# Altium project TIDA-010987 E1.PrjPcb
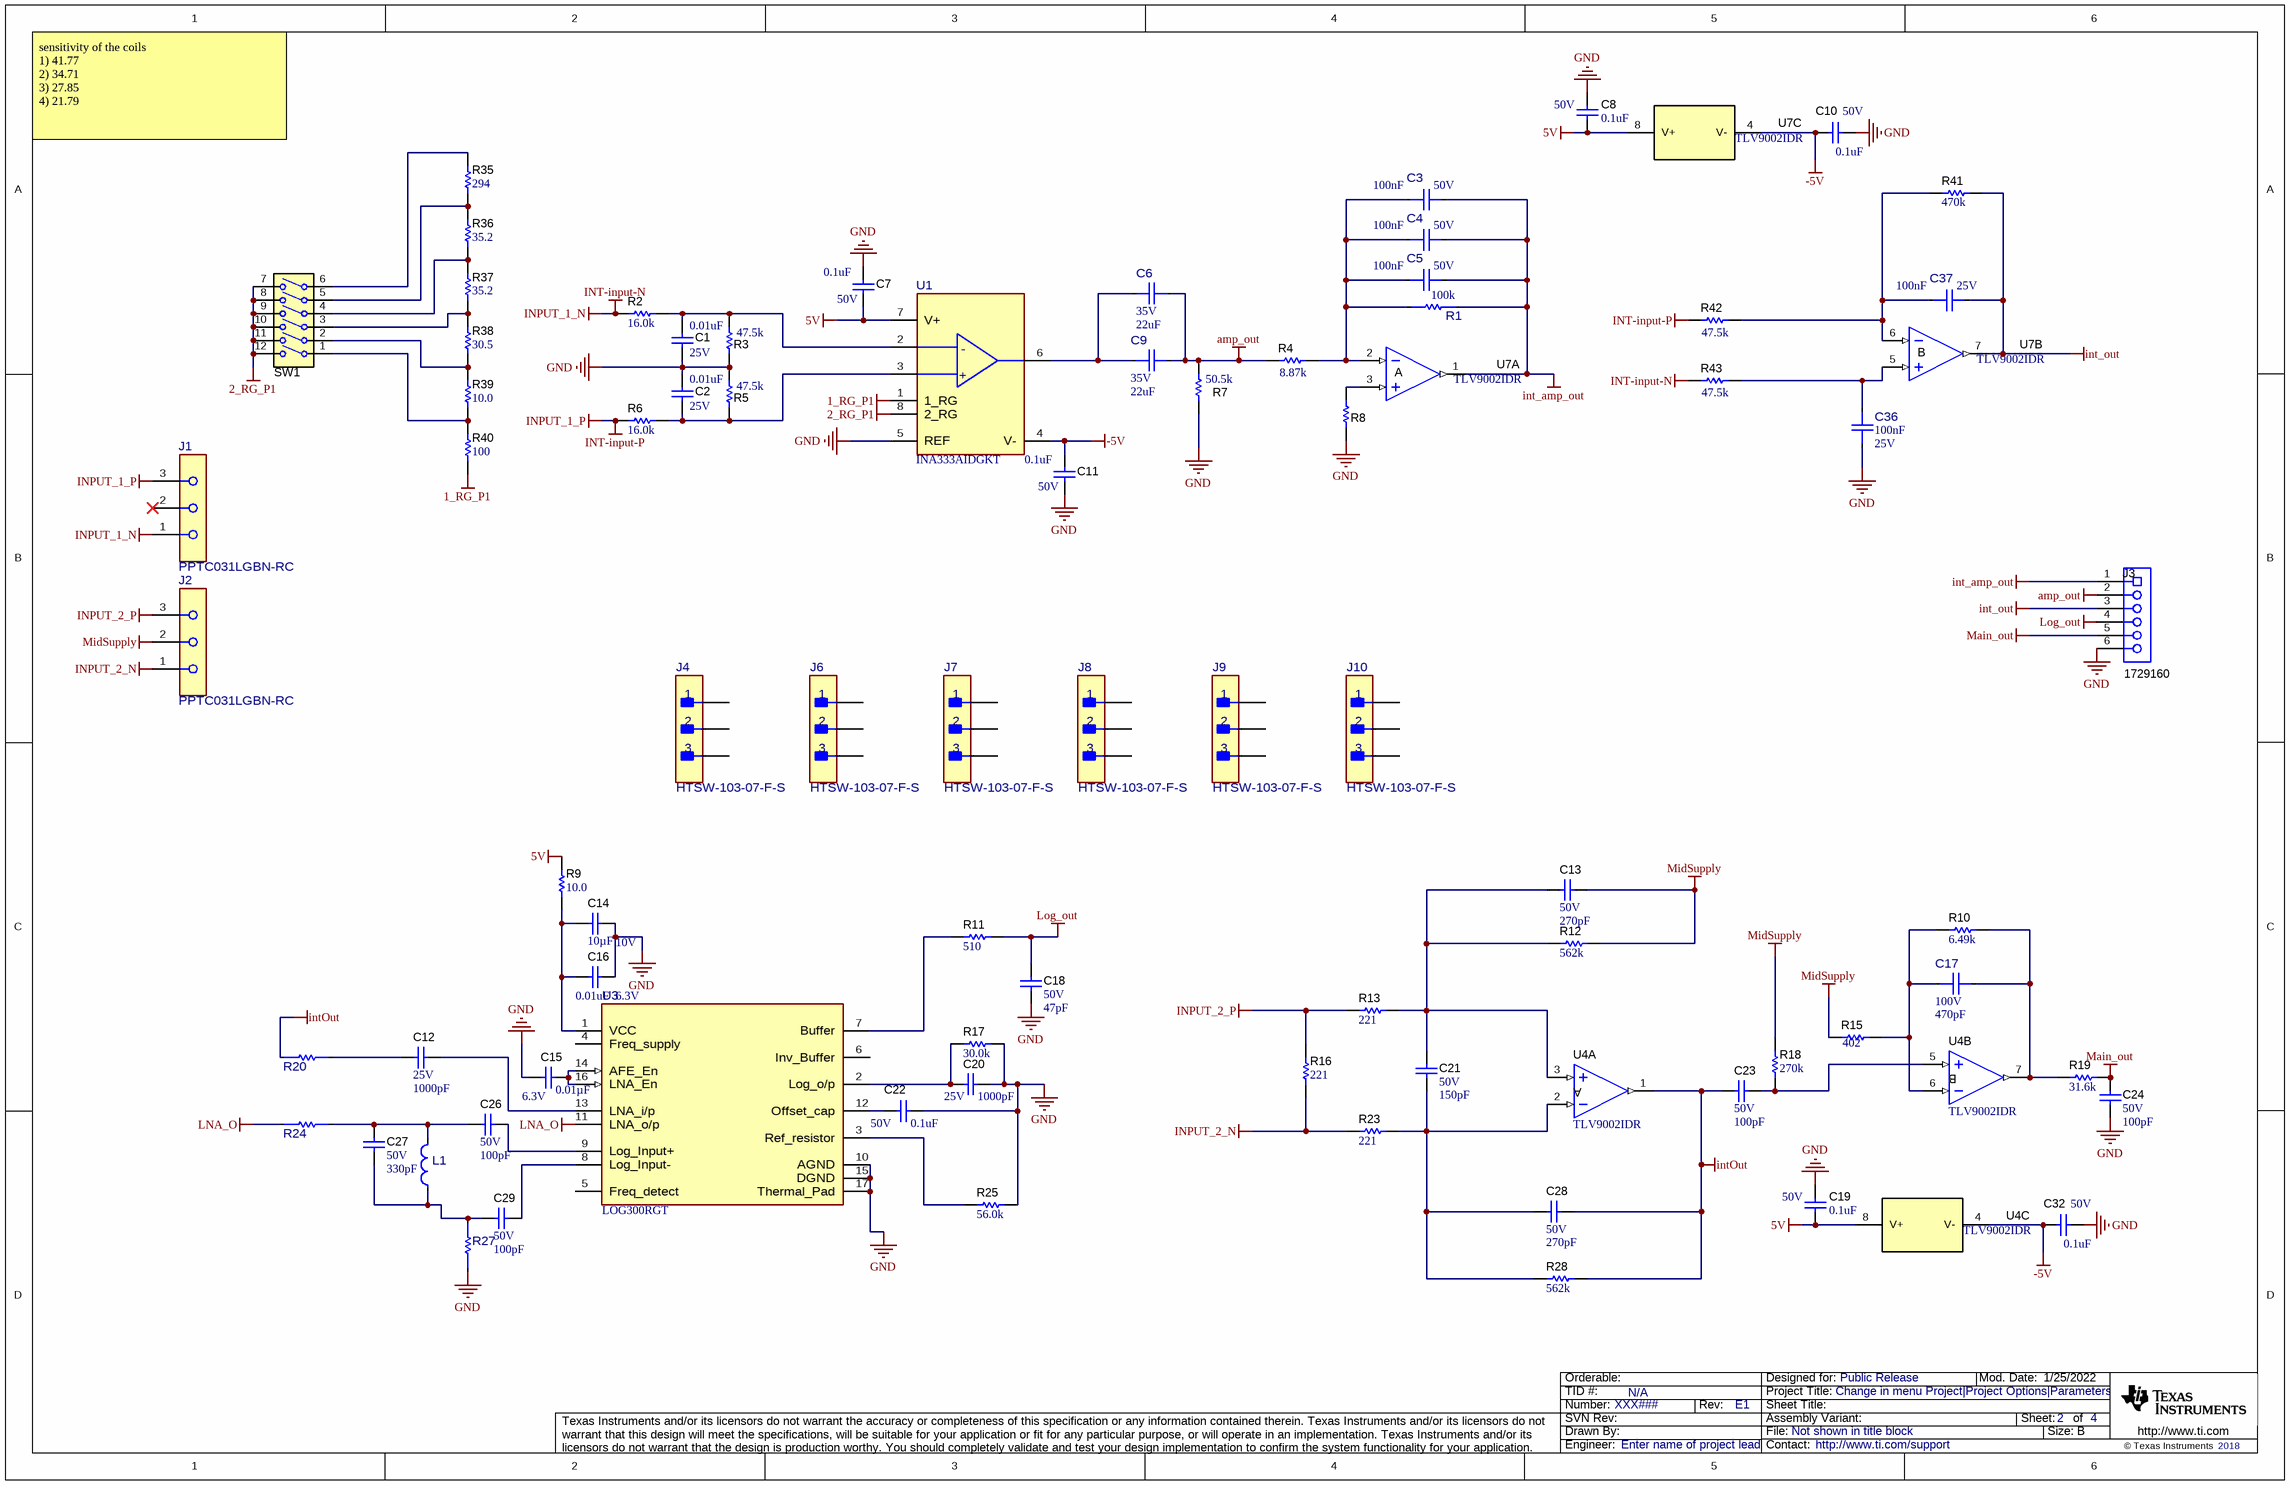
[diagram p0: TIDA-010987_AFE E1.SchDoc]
CopyrightYear: 2018; PCB_Layout: Who did the Layout?; PCB_Rev: E1; PRJ_Customer: Public Release; PRJ_Engineer: Enter name of project lead; PRJ_Number: XXX###; PRJ_Title: Change in menu Project|Project Options|Parameters; SCH_Rev: E1; TechSupport: http://www.ti.com/support; TID: N/A
2 sheets, 89 parts. Net scope: global (net labels, ports and power ports of the same name join across sheets).
Board file: TIDA-010987 E1.PcbDoc
Sheets:
  TIDA-010987_AFE E1.SchDoc
  TIDA-010987_Power E1.SchDoc

## Sheet TIDA-010987_AFE E1.SchDoc
size 431 x 279 mm; Date: Not shown in title block; ApprovedBy: Not shown in title block; CheckedBy: Not shown in title block; Author: Not shown in title block; CompanyName: Not shown in title block; Engineer: Not shown in title block; Organization: Not shown in title block; Address1: Not shown in title block; Address2: Not shown in title block; Address3: Not shown in title block; Address4: Not shown in title block; DocumentNumber: 2; Revision: Use project parameter SCH_Rev; SheetNumber: 2; SheetTotal: 4; PageSetup: Record=PageOptions¦CenterHorizontal=True¦CenterVertical=True¦PrintScale=1.00¦XCorrection=1.00¦YCorrection=1.00¦PrintKind=0¦BorderSize=5000000¦LeftOffset=0¦BottomOffset=0¦Orientation=2¦PaperLength=1000¦PaperWidth=1000¦Scale=100¦PaperSource=15¦PrintQuality=600¦MediaType=1¦DitherType=10¦PaperKind=Letter¦PrintScaleMode=1

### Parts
C1  value 0.01uF  VDC_V: 25V  [0603]  (hidden comment: C0603H103J3GACTU)
C2  value 0.01uF  VDC_V: 25V  [0603]  (hidden comment: C0603H103J3GACTU)
C3  value 100nF  VDC_V: 50V  [FP-GRMJN65C1H104GE01J_0704-MFG]  (hidden comment: GRMJN65C1H104GE01J)
C4  value 100nF  VDC_V: 50V  [FP-GRMJN65C1H104GE01J_0704-MFG]  (hidden comment: GRMJN65C1H104GE01J)
C5  value 100nF  VDC_V: 50V  [FP-GRMJN65C1H104GE01J_0704-MFG]  (hidden comment: GRMJN65C1H104GE01J)
C6  VDC_V: 35V  ValueDisplayed: 22uF  [FP-GMC21X5R226M35NT_0805-MFG]  (hidden comment: GMC21X5R226M35NT)
C7  value 0.1uF  VDC_V: 50V  [0603]  (hidden comment: 06035C104JAT2A)
C8  value 0.1uF  VDC_V: 50V  [0603]  (hidden comment: 06035C104JAT2A)
C9  VDC_V: 35V  ValueDisplayed: 22uF  [FP-GMC21X5R226M35NT_0805-MFG]  (hidden comment: GMC21X5R226M35NT)
C10  value 0.1uF  VDC_V: 50V  [0603]  (hidden comment: 06035C104JAT2A)
C11  value 0.1uF  VDC_V: 50V  [0603]  (hidden comment: 06035C104JAT2A)
C12  VDC_V: 25V  ValueDisplayed: 1000pF  [0603]  (hidden comment: GRM1885C1E102JA01D)
C13  VDC_V: 50V  ValueDisplayed: 270pF  [0603]  (hidden comment: C0603C271J5GACTU)
C14  Cap_F: 10µF  VDC_V: 10V  [0603]  (hidden comment: GRM188Z71A106MA73D)
C15  VDC_V: 6.3V  ValueDisplayed: 0.01µF  [0402]  (hidden comment: 0402B103K6R3CT)
C16  VDC_V: 6.3V  ValueDisplayed: 0.01uF  [0402]  (hidden comment: GRM155R70J103KA01D)
C17  VDC_V: 100V  ValueDisplayed: 470pF  [FP-GCM1885C2A471JA16D_0603-MFG]  (hidden comment: GCM1885C2A471JA16D)
C18  VDC_V: 50V  ValueDisplayed: 47pF  [0603]  (hidden comment: GRM1885C1H470JA01D)
C19  value 0.1uF  VDC_V: 50V  [0603]  (hidden comment: 06035C104JAT2A)
C20  VDC_V: 25V  ValueDisplayed: 1000pF  [0603]  (hidden comment: GRM1885C1E102JA01D)
C21  VDC_V: 50V  ValueDisplayed: 150pF  [0603]  (hidden comment: GRM1885C1H151JA01D)
C22  value 0.1uF  VDC_V: 50V  [0603]  (hidden comment: 06035C104JAT2A)
C23  VDC_V: 50V  ValueDisplayed: 100pF  [0603]  (hidden comment: 06035A101JAT2A)
C24  VDC_V: 50V  ValueDisplayed: 100pF  [0603]  (hidden comment: 06035A101JAT2A)
C26  VDC_V: 50V  ValueDisplayed: 100pF  [0603]  (hidden comment: 06035A101JAT2A)
C27  VDC_V: 50V  ValueDisplayed: 330pF  [0603]  (hidden comment: GRM1885C1H331JA01D)
C28  VDC_V: 50V  ValueDisplayed: 270pF  [0603]  (hidden comment: C0603C271J5GACTU)
C29  VDC_V: 50V  ValueDisplayed: 100pF  [0603]  (hidden comment: 06035A101JAT2A)
C32  value 0.1uF  VDC_V: 50V  [0603]  (hidden comment: 06035C104JAT2A)
C36  value 100nF  VDC_V: 25V  [FP-AC0805KRX7R8BB104_0805-MFG]  (hidden comment: AC0805KRX7R8BB104)
C37  value 100nF  VDC_V: 25V  [FP-AC0805KRX7R8BB104_0805-MFG]  (hidden comment: AC0805KRX7R8BB104)
J1  PPTC031LGBN-RC  [FP-PPTC031LGBN-RC_HDR3-MFG]
J2  PPTC031LGBN-RC  [FP-PPTC031LGBN-RC_HDR3-MFG]
J3  1729160  [Phoenix_1729160]
J4  HTSW-103-07-F-S  [FP-HTSW-103-07-F-S_HDR3-MFG]
J6  HTSW-103-07-F-S  [FP-HTSW-103-07-F-S_HDR3-MFG]
J7  HTSW-103-07-F-S  [FP-HTSW-103-07-F-S_HDR3-MFG]
J8  HTSW-103-07-F-S  [FP-HTSW-103-07-F-S_HDR3-MFG]
J9  HTSW-103-07-F-S  [FP-HTSW-103-07-F-S_HDR3-MFG]
J10  HTSW-103-07-F-S  [FP-HTSW-103-07-F-S_HDR3-MFG]
L1  MLF1608DR68MTA00  [FP-MLF1608DR68MTA00_0603-MFG]  (value not drawn)
R1  value 100k  [FP-ERA-3AEB104V_0603-MFG]  (hidden comment: ERA-3AEB104V)
R2  value 16.0k  [0603]  (hidden comment: RT0603BRD0716KL)
R3  value 47.5k  [0603]  (hidden comment: RT0603BRD0747K5L)
R4  value 8.87k  [0603]  (hidden comment: RT0603BRD078K87L)
R5  value 47.5k  [0603]  (hidden comment: RT0603BRD0747K5L)
R6  value 16.0k  [0603]  (hidden comment: RT0603BRD0716KL)
R7  value 50.5k  [0603]  (hidden comment: RT0603BRD0750K5L)
R8  RT0603BRD079K88L  [0603]  (value not drawn)
R9  ValueDisplayed: 10.0  [0402]  (hidden comment: MCR01MZPF10R0)
R10  ValueDisplayed: 6.49k  [0603]  (hidden comment: RT0603BRD076K49L)
R11  ValueDisplayed: 510  [0603]  (hidden comment: RG1608P-511-B-T5)
R12  ValueDisplayed: 562k  [0603]  (hidden comment: RT0603BRD07562KL)
R13  ValueDisplayed: 221  [0603]  (hidden comment: RG1608P-2210-B-T5)
R15  ValueDisplayed: 402  [0603]  (hidden comment: RC0603FR-07402RL)
R16  ValueDisplayed: 221  [0603]  (hidden comment: RG1608P-2210-B-T5)
R17  ValueDisplayed: 30.0k  [0603]  (hidden comment: RC0603FR-0730KL)
R18  ValueDisplayed: 270k  [0603]  (hidden comment: RG1608P-274-B-T5)
R19  ValueDisplayed: 31.6k  [0603]  (hidden comment: RC0603FR-0731K6L)
R20  RC0603FR-100RL  [FP-RC0603FR-100RL_0603-MFG]  (value not drawn)
R23  ValueDisplayed: 221  [0603]  (hidden comment: RG1608P-2210-B-T5)
R24  RC0603FR-100RL  [FP-RC0603FR-100RL_0603-MFG]  (value not drawn)
R25  ValueDisplayed: 56.0k  [0603]  (hidden comment: RG1608P-563-B-T5)
R27  RC0603FR-100RL  [FP-RC0603FR-100RL_0603-MFG]  (value not drawn)
R28  ValueDisplayed: 562k  [0603]  (hidden comment: RT0603BRD07562KL)
R35  ValueDisplayed: 294  [0603]  (hidden comment: RT0603BRD07294RL)
R36  ValueDisplayed: 35.2  [0603]  (hidden comment: RT0603BRD0735R2L)
R37  ValueDisplayed: 35.2  [0603]  (hidden comment: RT0603BRD0735R2L)
R38  ValueDisplayed: 30.5  [0603]  (hidden comment: RT0603BRD0730R5L)
R39  ValueDisplayed: 10.0  [0603]  (hidden comment: RT0603BRD0710RL)
R40  ValueDisplayed: 100  [0603]  (hidden comment: ERA-3AEB101V)
R41  ValueDisplayed: 470k  [0603]  (hidden comment: RT0603BRD07470KL)
R42  value 47.5k  [0603]  (hidden comment: RG1608P-4752-B-T5)
R43  value 47.5k  [0603]  (hidden comment: RG1608P-4752-B-T5)
SW1  76SB06ST  [SW_76SB06]  (value not drawn)
U1  INA333AIDGKT  [DGK0008A-MFG]
U3  LOG300RGT  [RGT0016A-MFG]
U4  TLV9002IDR  [D0008A_N]  (parts A,B,C of 3)
U7  TLV9002IDR  [D0008A_N]  (parts A,B,C of 3)

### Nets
1_RG_P1: R40.1 U1.1(1_RG)
2_RG_P1: SW1.7(6A) SW1.8(5A) SW1.9(4A) SW1.10(3A) SW1.11(2A) SW1.12(1A) U1.8(2_RG)
5V: C7.2 C8.2 C19.2 R9.2 U1.7(V+) U4.8(V+) U7.8(V+)
-5V: C10.2 C11.1 C32.2 U1.4(V-) U4.4(V-) U7.4(V-)
amp_out: C6.1 C9.2 J3.2 R4.1 R7.1
GND: C1.2 C2.1 C7.1 C8.1 C10.1 C11.2 C14.1 C15.2 C16.1 C18.2 C19.1 C20.1 C22.1 C24.2 C32.1 C36.1 J3.6 R3.1 R5.2 R7.2 R8.1 R17.1 R25.2 R27.1 U1.5(REF) U3.10(AGND) U3.15(DGND) U3.17(Thermal_Pad)
INPUT_1_N: J1.1 R2.2 R43.1  [also labelled INT-input-N]
INPUT_1_P: J1.3 R6.2 R42.1  [also labelled INT-input-P]
INPUT_2_N: J2.1 R16.1 R23.1
INPUT_2_P: J2.3 R13.1 R16.2
int_amp_out: C3.2 C4.2 C5.2 J3.1 R1.1 U7.1(OUT)
int_out: C37.2 J3.3 R41.2 U7.7(OUT)
intOut: C23.2 C28.1 R20.1 R28.2 U4.1(OUT)
LNA_O: R24.1 U3.11(LNA_o/p)
Log_out: C18.1 J3.4 R11.2
Main_out: C24.1 J3.5 R19.2
MidSupply: C13.1 J2.2 R12.2 R15.1 R18.2
NetC1_1: C1.1 R2.1 R3.2 U1.2(VIN-)
NetC2_2: C2.2 R5.1 R6.1 U1.3(VIN+)
NetC3_1: C3.1 C4.1 C5.1 R1.2 R4.2 U7.2(IN-)
NetC6_2: C6.2 C9.1 U1.6(VOUT)
NetC12_1: C12.1 U3.13(LNA_i/p)
NetC12_2: C12.2 R20.2
NetC13_2: C13.2 C21.1 R12.1 R13.2 U4.3(IN+)
NetC14_2: C14.2 C16.2 R9.1 U3.1(VCC)
NetC15_1: C15.1 U3.14(AFE_En) U3.16(LNA_En)
NetC17_1: C17.1 R10.1 R15.2 U4.6(IN-)
NetC17_2: C17.2 R10.2 R19.1 U4.7(OUT)
NetC20_2: C20.2 R17.2 U3.2(Log_o/p)
NetC21_2: C21.2 C28.2 R23.2 R28.1 U4.2(IN-)
NetC22_2: C22.2 U3.12(Offset_cap)
NetC23_1: C23.1 R18.1 U4.5(IN+)
NetC26_1: C26.1 C27.1 L1.2 R24.2
NetC26_2: C26.2 U3.9(Log_Input+)
NetC27_2: C27.2 C29.1 L1.1 R27.2
NetC29_2: C29.2 U3.8(Log_Input-)
NetC36_2: C36.2 R43.2 U7.5(IN+)
NetC37_1: C37.1 R41.1 R42.2 U7.6(IN-)
NetR8_2: R8.2 U7.3(IN+)
NetR11_1: R11.1 U3.7(Buffer)
NetR25_1: R25.1 U3.3(Ref_resistor)
NetR35_1: R35.1 R36.2 SW1.5
NetR35_2: R35.2 SW1.6
NetR36_1: R36.1 R37.2 SW1.4
NetR37_1: R37.1 R38.2 SW1.3
NetR38_1: R38.1 R39.2 SW1.2
NetR39_1: R39.1 R40.2 SW1.1

Not connected (* = marked no-connect by the designer): J1 2*; J4 1 2 3; J6 1 2 3; J7 1 2 3; J8 1 2 3; J9 1 2 3; J10 1 2 3; U3 4(Freq_supply) 5(Freq_detect) 6(Inv_Buffer)

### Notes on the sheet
- sensitivity of the coils
  1) 41.77
  2) 34.71
  3) 27.85
  4) 21.79

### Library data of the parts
C1 C2 = CMP-0006975-4: CAP, CERM, 0.01 uF, 25 V, +/- 5%, C0G/NP0, 0603; Manufacturer: Kemet; SizeZ_mm: 1; Cap_F: 10nF; TaMin_C: -55°C; Polarized: N; SizeAreaWB_mm2: 4.68; U/M: EA; TaMax_C: 200°C; SizeX_mm: 1.6; SizeY_mm: 0.8; SizeArea_mm2: 1.28; AEC Category: Q200; Value1: Unknown
C3-C5 = CMP-0125654-1: 0.1 µF ±2% 50V Ceramic Capacitor C0G, NP0 0704 (1810 Metric); Manufacturer: Murata; TempCo: 30ppm/°C; SizeZ_mm: 0.65mm; AEC Qualified: No; ValueDisplayed: 0.1uF
C6 C9 = CMP-0120897-1: 22 µF ±20% 35V Ceramic Capacitor X5R 0805 (2012 Metric); Manufacturer: Cal-Chip Electronics; TempCo: 15%; Value: 22µF; SizeZ_mm: 1.45mm; AEC Qualified: No
C7 C8 C10 C11 C19 C22 C32 = CMP-0083854-1: CAP, CERM, 0.1 µF, 50 V,+/- 5%, X7R, 0603; Manufacturer: AVX; SizeZ_mm: 1; AEC Qualified: N; Cap_F: 100nF; ValueDisplayed: 0.1µF; TaMin_C: -55°C; Green_Lifecycle: Active; SizeAreaWB_mm2: 4.68; Green_REACh: Passed; U/M: EA; TaMax_C: 125°C; SizeX_mm: 1.6; SizeY_mm: 0.8; SizeArea_mm2: 1.28; AEC Category: Q200
C12 C20 = CMP-0007159-4: CAP, CERM, 1000 pF, 25 V, +/- 5%, C0G/NP0, 0603; Manufacturer: MuRata; TaMin_C: -55°C; Polarized: N; SizeAreaWB_mm2: 4.68; Value1: Unknown; U/M: EA; Value: 1000pF; TaMax_C: 125°C; SizeZ_mm: 1; SizeX_mm: 1.6; SizeY_mm: 0.8; SizeArea_mm2: 1.28; Cap_F: 1nF; AEC Category: Q200
C13 C28 = CMP-0006910-4: CAP, CERM, 270 pF, 50 V, +/- 5%, C0G/NP0, 0603; Manufacturer: Kemet; TaMin_C: -55°C; Polarized: N; SizeAreaWB_mm2: 4.68; Value1: Unknown; U/M: EA; Value: 270pF; TaMax_C: 125°C; SizeZ_mm: 1; SizeX_mm: 1.6; SizeY_mm: 0.8; SizeArea_mm2: 1.28; AEC Category: Q200
C14 = CMP-0007497-5: CAP, CERM, 10 uF, 10 V, +/- 20%, X7R, 0603; Manufacturer: MuRata; TaMin_C: -55°C; Polarized: N; SizeAreaWB_mm2: 4.68; Value1: Unknown; U/M: EA; Value: 10uF; TaMax_C: 125°C; SizeZ_mm: 1; SizeX_mm: 1.6; SizeY_mm: 0.8; SizeArea_mm2: 1.28; AEC Category: Q200
C15 = CMP-0860544-1: CAP, CERM, 0.01 µF, 6.3 V,+/- 10%, X7R, 0402; Manufacturer: Walsin; Value: 0.01uF; SizeY_mm: 0.5; SizeX_mm: 1; SizeZ_mm: 0.6; AEC Category: Q200; SizeAreaWB_mm2: 3; TaMax_C: 125°C; U/M: EA; AEC Qualified: N; Cap_F: 10nF; TaMin_C: -55°C
C16 = CMP-0006622-2: CAP, CERM, 0.01 uF, 6.3 V, +/- 10%, X7R, 0402; Manufacturer: MuRata; TaMin_C: -55°C; Polarized: N; SizeAreaWB_mm2: 3; Value1: Unknown; U/M: EA; Value: 0.01uF; TaMax_C: 125°C; SizeZ_mm: 0.6; SizeX_mm: 1; SizeY_mm: 0.5; Cap_F: 10nF; AEC Category: Q200
C17 = CMP-0090211-1: 470pF ±5% 100V Ceramic Capacitor C0G, NP0 0603 (1608 Metric); Manufacturer: Murata Electronics North America; TempCo: 30ppm/°C; SizeZ_mm: 0.9mm; AEC Qualified: Yes; AEC Grade: Grade 1
C18 = CMP-0007220-4: CAP, CERM, 47 pF, 50 V, +/- 5%, C0G/NP0, 0603; Manufacturer: MuRata; TaMin_C: -55°C; Polarized: N; SizeAreaWB_mm2: 4.68; Value1: Unknown; U/M: EA; Value: 47pF; TaMax_C: 125°C; SizeZ_mm: 1; SizeX_mm: 1.6; SizeY_mm: 0.8; SizeArea_mm2: 1.28; AEC Category: Q200
C21 = CMP-0007185-4: CAP, CERM, 150 pF, 50 V, +/- 5%, C0G/NP0, 0603; Manufacturer: MuRata; TaMin_C: -55°C; Polarized: N; SizeAreaWB_mm2: 4.68; Value1: Unknown; U/M: EA; Value: 150pF; TaMax_C: 125°C; SizeZ_mm: 1; SizeX_mm: 1.6; SizeY_mm: 0.8; SizeArea_mm2: 1.28; AEC Category: Q200
C23 C24 C26 C29 = CMP-0006763-4: CAP, CERM, 100 pF, 50 V, +/- 5%, C0G/NP0, 0603; Manufacturer: AVX; TaMin_C: -55°C; ESR_ohm: 1.19d; Polarized: N; SizeAreaWB_mm2: 4.68; Value1: 0.119 ohm; U/M: EA; Value: 100pF; TaMax_C: 125°C; SizeZ_mm: 1; SizeX_mm: 1.6; SizeY_mm: 0.8; SizeArea_mm2: 1.28; AEC Category: Q200
C27 = CMP-0007209-4: CAP, CERM, 330 pF, 50 V, +/- 5%, C0G/NP0, 0603; Manufacturer: MuRata; TaMin_C: -55°C; Polarized: N; SizeAreaWB_mm2: 4.68; Value1: Unknown; U/M: EA; Value: 330pF; TaMax_C: 125°C; SizeZ_mm: 1; SizeX_mm: 1.6; SizeY_mm: 0.8; SizeArea_mm2: 1.28; AEC Category: Q200
C36 C37 = CMP-0121355-1: 0.1 µF ±10% 25V Ceramic Capacitor X7R 0805 (2012 Metric); Manufacturer: Yageo; TempCo: 15%; SizeZ_mm: 0.95mm; AEC Qualified: Yes; AEC Grade: Grade 1
J1 J2 = CMP-0122423-2: 3 Position Header Connector 0.100" (2.54mm) Through Hole, Right Angle Tin; Manufacturer: Sullins; ContactFinish: Tin,Nickel; Current_A: 3A; Row_Count: 1; Voltage_V: 250V; AEC Qualified: No; Conn Gender: Female; Is Female: yes; SizeZ_mm: 2.74mm
J3 = CMP-0055492-1: Terminal Block, 6x1, 5.08mm, Th; Manufacturer: Phoenix Contact; CNHeader: FALSE; CT: TRUE
J4 J6-J10 = CMP-0096279-1: Connector Header Through Hole 3 position 0.100" (2.54mm); Manufacturer: Samtec; SizeZ_mm: 8.71mm; ContactFinish: Gold,Nickel; Conn Gender: Male; AEC Qualified: No; Row_Count: 1; Conn Orientation: Straight
L1 = CMP-0125407-1: Ind Power Shielded Multi-Layer 680nH 20% 25MHz 15Q-Factor Ferrite 70mA 0603 Punched Paper T/R; Manufacturer: TDK; AEC Qualified: No; DCR_ohm: 1.25; SizeZ_mm: 0.95mm; Q Factor: 15; Self Resonant Frequency: 150MHz; Shrouded: true
R1 = CMP-0046061-1: Res Thin Film 0603 100K Ohm 0.1% 0.1W ±25ppm/°C Molded SMD Punched Carrier T/R; Manufacturer: Panasonic; Power_W: 100mW; SizeZ_mm: 0.55mm; AEC Qualified: Yes; VDC_V: 75V; AEC Grade: Grade 0
R2 R6 = CMP-0023803-3: RES, 16.0 k, 0.1%, 0.1 W, 0603; Manufacturer: Yageo America; Power_W: 100mW; TempCo: 25 ppm/C; Value_Code: 16k0; U/M: EA; EIA_Code: E192; SizeX_mm: 1.6; SizeY_mm: 0.8; SizeZ_mm: 1; Value2: 0.1W; SizeArea_mm2: 1.28; VDC_V: 75V; AEC Category: Q200; Res_ohm: 16k
R3 R5 = CMP-0024266-3: RES, 47.5 k, 0.1%, 0.1 W, 0603; Manufacturer: Yageo America; Power_W: 100mW; TempCo: 25 ppm/C; Value_Code: 47k5; U/M: EA; EIA_Code: E192; SizeX_mm: 1.6; SizeY_mm: 0.8; SizeZ_mm: 1; Value2: 0.1W; SizeArea_mm2: 1.28; VDC_V: 75V; AEC Category: Q200
R4 = CMP-0024525-2: RES, 8.87 k, 0.1%, 0.1 W, 0603; Manufacturer: Yageo America; Power_W: 100mW; TempCo: 25 ppm/C; Value_Code: 8k87; EIA_Code: E192; SizeX_mm: 1.6; SizeY_mm: 0.8; SizeZ_mm: 1; Value2: 0.1W; SizeArea_mm2: 1.28; VDC_V: 75V; AEC Category: Q200; U/M: EA
R7 = CMP-0024307-2: RES, 50.5 k, 0.1%, 0.1 W, 0603; Manufacturer: Yageo America; Power_W: 100mW; TempCo: 25 ppm/C; Value_Code: 50k5; EIA_Code: E192; SizeX_mm: 1.6; SizeY_mm: 0.8; SizeZ_mm: 1; Value2: 0.1W; SizeArea_mm2: 1.28; VDC_V: 75V; AEC Category: Q200; U/M: EA
R8 = CMP-0024558-2: RES, 9.88 k, 0.1%, 0.1 W, 0603; Manufacturer: Yageo America; Power_W: 100mW; TempCo: 25 ppm/C; Value_Code: 9k88; U/M: EA; Value: 9.88k; EIA_Code: E192; SizeX_mm: 1.6; SizeY_mm: 0.8; SizeZ_mm: 1; Value2: 0.1W; SizeArea_mm2: 1.28; VDC_V: 75V; AEC Category: Q200
R9 = CMP-0026717-1: RES, 10.0, 1%, 0.063 W, 0402; Manufacturer: Rohm; Power_W: 63mW; TempCo: 100 ppm/C; Value_Code: 10R0; U/M: EA; Value: 10.0; EIA_Code: E96; Res_ohm: 10; SizeX_mm: 1; SizeY_mm: 0.5; SizeZ_mm: 0.6; Value2: 0.063W; AEC Qualified: N; VDC_V: 50V; AEC Category: Q200
R10 = CMP-0024436-2: RES, 6.49 k, 0.1%, 0.1 W, 0603; Manufacturer: Yageo America; Power_W: 100mW; TempCo: 25 ppm/C; Value_Code: 6k49; U/M: EA; Value: 6.49k; EIA_Code: E192; SizeX_mm: 1.6; SizeY_mm: 0.8; SizeZ_mm: 1; Value2: 0.1W; SizeArea_mm2: 1.28; VDC_V: 75V; AEC Category: Q200
R11 = CMP-0023567-3: RES, 510, 0.1%, 0.1 W, 0603; Manufacturer: Susumu Co Ltd; Power_W: 100mW; TempCo: 25 ppm/C; Value_Code: 510R; U/M: EA; Value: 510; SizeX_mm: 1.6; SizeY_mm: 0.8; SizeZ_mm: 1; Value2: 0.1W; SizeArea_mm2: 1.28; VDC_V: 75V; AEC Category: Q200
R12 R28 = CMP-0024341-3: RES, 562 k, 0.1%, 0.1 W, 0603; Manufacturer: Yageo America; Power_W: 100mW; TempCo: 25 ppm/C; U/M: EA; Value: 562k; EIA_Code: E192; SizeX_mm: 1.6; SizeY_mm: 0.8; SizeZ_mm: 1; Value2: 0.1W; SizeArea_mm2: 1.28; VDC_V: 75V; AEC Category: Q200
R13 R16 R23 = CMP-0023468-3: RES, 221, 0.1%, 0.1 W, 0603; Manufacturer: Susumu Co Ltd; Power_W: 100mW; TempCo: 25 ppm/C; Value_Code: 221R; U/M: EA; Value: 221; EIA_Code: E192; SizeX_mm: 1.6; SizeY_mm: 0.8; SizeZ_mm: 1; Value2: 0.1W; SizeArea_mm2: 1.28; VDC_V: 75V; AEC Category: Q200
R15 = CMP-0023097-5: RES, 402, 1%, 0.1 W, 0603; Manufacturer: Yageo; Power_W: 100mW; TempCo: 100 ppm/C; Value_Code: 402R; Value: 402; EIA_Code: E96; SizeX_mm: 1.6; SizeY_mm: 0.8; SizeZ_mm: 1; Value2: 0.1W; SizeArea_mm2: 1.28; AEC Qualified: N; VDC_V: 75V; AEC Category: Q200; SizeAreaWB_mm2: 4.68
R17 = CMP-0023020-5: RES, 30.0 k, 1%, 0.1 W, 0603; Manufacturer: Yageo; Power_W: 100mW; TempCo: 100 ppm/C; Value_Code: 30k0; Value: 30.0k; Res_ohm: 30k; SizeX_mm: 1.6; SizeY_mm: 0.8; SizeZ_mm: 1; Value2: 0.1W; SizeArea_mm2: 1.28; AEC Qualified: N; VDC_V: 75V; AEC Category: Q200; SizeAreaWB_mm2: 4.68
R18 = CMP-0023500-3: RES, 270 k, 0.1%, 0.1 W, 0603; Manufacturer: Susumu Co Ltd; Power_W: 100mW; TempCo: 25 ppm/C; Value: 270k; SizeX_mm: 1.6; SizeY_mm: 0.8; SizeZ_mm: 1; Value2: 0.1W; SizeArea_mm2: 1.28; VDC_V: 75V; AEC Category: Q200; U/M: EA
R19 = CMP-0023026-5: RES, 31.6 k, 1%, 0.1 W, 0603; Manufacturer: Yageo; Power_W: 100mW; TempCo: 100 ppm/C; Value_Code: 31k6; Value: 31.6k; EIA_Code: E96; SizeX_mm: 1.6; SizeY_mm: 0.8; SizeZ_mm: 1; Value2: 0.1W; SizeArea_mm2: 1.28; AEC Qualified: N; VDC_V: 75V; AEC Category: Q200; SizeAreaWB_mm2: 4.68
R20 R24 R27 = CMP-0123755-1: 0 Ohms Jumper Chip Resistor 0603 (1608 Metric) Moisture Resistant Thick Film; Manufacturer: Yageo; AEC Qualified: No; Res_ohm: 0; SizeZ_mm: 0.55mm; Tolerance_%: 1%; Value: 0
R25 = CMP-0023577-3: RES, 56.0 k, 0.1%, 0.1 W, 0603; Manufacturer: Susumu Co Ltd; Power_W: 100mW; TempCo: 25 ppm/C; Value_Code: 56k0; U/M: EA; Value: 56.0k; Res_ohm: 56k; SizeX_mm: 1.6; SizeY_mm: 0.8; SizeZ_mm: 1; Value2: 0.1W; SizeArea_mm2: 1.28; VDC_V: 75V; AEC Category: Q200
R35 = CMP-0024047-2: RES, 294, 0.1%, 0.1 W, 0603; Manufacturer: Yageo America; Power_W: 100mW; TempCo: 25 ppm/C; Value_Code: 294R; U/M: EA; Value: 294; EIA_Code: E192; SizeX_mm: 1.6; SizeY_mm: 0.8; SizeZ_mm: 1; Value2: 0.1W; SizeArea_mm2: 1.28; VDC_V: 75V; AEC Category: Q200
R36 R37 = CMP-0024148-3: RES, 35.2, 0.1%, 0.1 W, 0603; Manufacturer: Yageo America; Power_W: 100mW; TempCo: 25 ppm/C; Value_Code: 35R2; U/M: EA; Value: 35.2; EIA_Code: E192; SizeX_mm: 1.6; SizeY_mm: 0.8; SizeZ_mm: 1; Value2: 0.1W; SizeArea_mm2: 1.28; VDC_V: 75V; AEC Category: Q200
R38 = CMP-0024100-3: RES, 30.5, 0.1%, 0.1 W, 0603; Manufacturer: Yageo America; Power_W: 100mW; TempCo: 25 ppm/C; Value_Code: 30R5; U/M: EA; Value: 30.5; EIA_Code: E192; SizeX_mm: 1.6; SizeY_mm: 0.8; SizeZ_mm: 1; Value2: 0.1W; SizeArea_mm2: 1.28; VDC_V: 75V; AEC Category: Q200
R39 = CMP-0023661-3: RES, 10.0, 0.1%, 0.1 W, 0603; Manufacturer: Yageo America; Power_W: 100mW; TempCo: 25 ppm/C; Value_Code: 10R0; U/M: EA; Value: 10.0; EIA_Code: E192; Res_ohm: 10; SizeX_mm: 1.6; SizeY_mm: 0.8; SizeZ_mm: 1; Value2: 0.1W; SizeArea_mm2: 1.28; VDC_V: 75V; AEC Category: Q200
R40 = CMP-0023361-3: RES, 100, 0.1%, 0.1 W, AEC-Q200 Grade 0, 0603; Manufacturer: Panasonic; Power_W: 100mW; TempCo: 25 ppm/C; Value_Code: 100R; U/M: EA; Value: 100; EIA_Code: E192; SizeX_mm: 1.6; SizeY_mm: 0.8; SizeZ_mm: 1; Value2: 0.1W; SizeArea_mm2: 1.28; AEC Qualified: Y; VDC_V: 75V; AEC Grade: 0; AEC Category: Q200
R41 = CMP-0024262-3: RES, 470 k, 0.1%, 0.1 W, 0603; Manufacturer: Yageo America; Power_W: 100mW; TempCo: 25 ppm/C; U/M: EA; Value: 470k; EIA_Code: E192; SizeX_mm: 1.6; SizeY_mm: 0.8; SizeZ_mm: 1; Value2: 0.1W; SizeArea_mm2: 1.28; VDC_V: 75V; AEC Category: Q200
R42 R43 = CMP-0023559-3: RES, 47.5 k, 0.1%, 0.1 W, 0603; Manufacturer: Susumu Co Ltd; Power_W: 100mW; TempCo: 25 ppm/C; Value_Code: 47k5; EIA_Code: E192; SizeX_mm: 1.6; SizeY_mm: 0.8; SizeZ_mm: 1; Value2: 0.1W; SizeArea_mm2: 1.28; VDC_V: 75V; AEC Category: Q200; U/M: EA
SW1 = CMP-0002309-1: Switch, SPST, Off-On, 6 Pos, 0.15 A, 30 VDC, TH; Manufacturer: Grayhill; PositionCount: 6; SizeZ_mm: 8.13; VDC_V: 30V; CurrentRating_mA: 150A; SizeX_mm: 9.65; SizeY_mm: 17.3; SizeArea_mm2: 166.945; SizeAreaWB_mm2: 224.845
U1 = CMP-0089145-1: Instrumentation Amplifier 1 Circuit Rail-to-Rail 8-VSSOP; Manufacturer: Texas Instruments; Voltage Gain: 0.001-1V/mV; AEC Qualified: No; Min Supply Voltage: 1.8V; TJmax_C: +150°C; Max Supply Voltage: 5.5V; Standoff Height: 0.05mm; Input Bias Current: 0.00007uA; SizeZ_mm: 1.1mm; Input Offset Voltage: 0.010-0.025mV; TaMin_C: -40°C; Max Dual Supply Voltage: 2.75V; TaMax_C: +125°C; Bandwidth: 150kHz; Nominal Supply Current: 50uA; Min Dual Supply Voltage: 900mV; Number Of Channels: 1; Import Ts: 1521844208; Ciiva Ids: 1154636
U3 = CMP-0122050-1: 80-MHz, Logarithmic Detector With Integrated Low-Noise Amplifier; Manufacturer: Texas Instruments; SizeZ_mm: 1mm; AEC Qualified: No; Bandwidth: 79.9999MHz; Max Supply Voltage: 5.25V; Min Supply Voltage: 3V; Standoff Height: 0mm; TaMax_C: +125°C; TaMin_C: -40°C; TJmax_C: +150°C
U4 U7 = CMP-0080747-1: 2-Channel, 1MHz, RRIO, 1.8V to 5.5V Operational Amplifier for Cost-Optimized Systems, D0008A (SOIC-8); Alternate Manufacturer: Texas Instruments; SizeAreaWB_mm2: 56.58; SizeZ_mm: 1.75; SizeX_mm: 4.9; SizeY_mm: 6.2; SizeArea_mm2: 30.38; CompType: IC; AEC Qualified: N; AEC Category: Q200

## Sheet TIDA-010987_Power E1.SchDoc
size 431 x 279 mm; Date: Not shown in title block; ApprovedBy: Not shown in title block; CheckedBy: Not shown in title block; Author: Not shown in title block; CompanyName: Not shown in title block; Engineer: Not shown in title block; Organization: Not shown in title block; Address1: Not shown in title block; Address2: Not shown in title block; Address3: Not shown in title block; Address4: Not shown in title block; DocumentNumber: 2; Revision: Use project parameter SCH_Rev; SheetNumber: 4; SheetTotal: 4; PageSetup: Record=PageOptions¦CenterHorizontal=True¦CenterVertical=True¦PrintScale=1.00¦XCorrection=1.00¦YCorrection=1.00¦PrintKind=0¦BorderSize=5000000¦LeftOffset=0¦BottomOffset=0¦Orientation=2¦PaperLength=1000¦PaperWidth=1000¦Scale=100¦PaperSource=15¦PrintQuality=600¦MediaType=1¦DitherType=10¦PaperKind=Letter¦PrintScaleMode=1
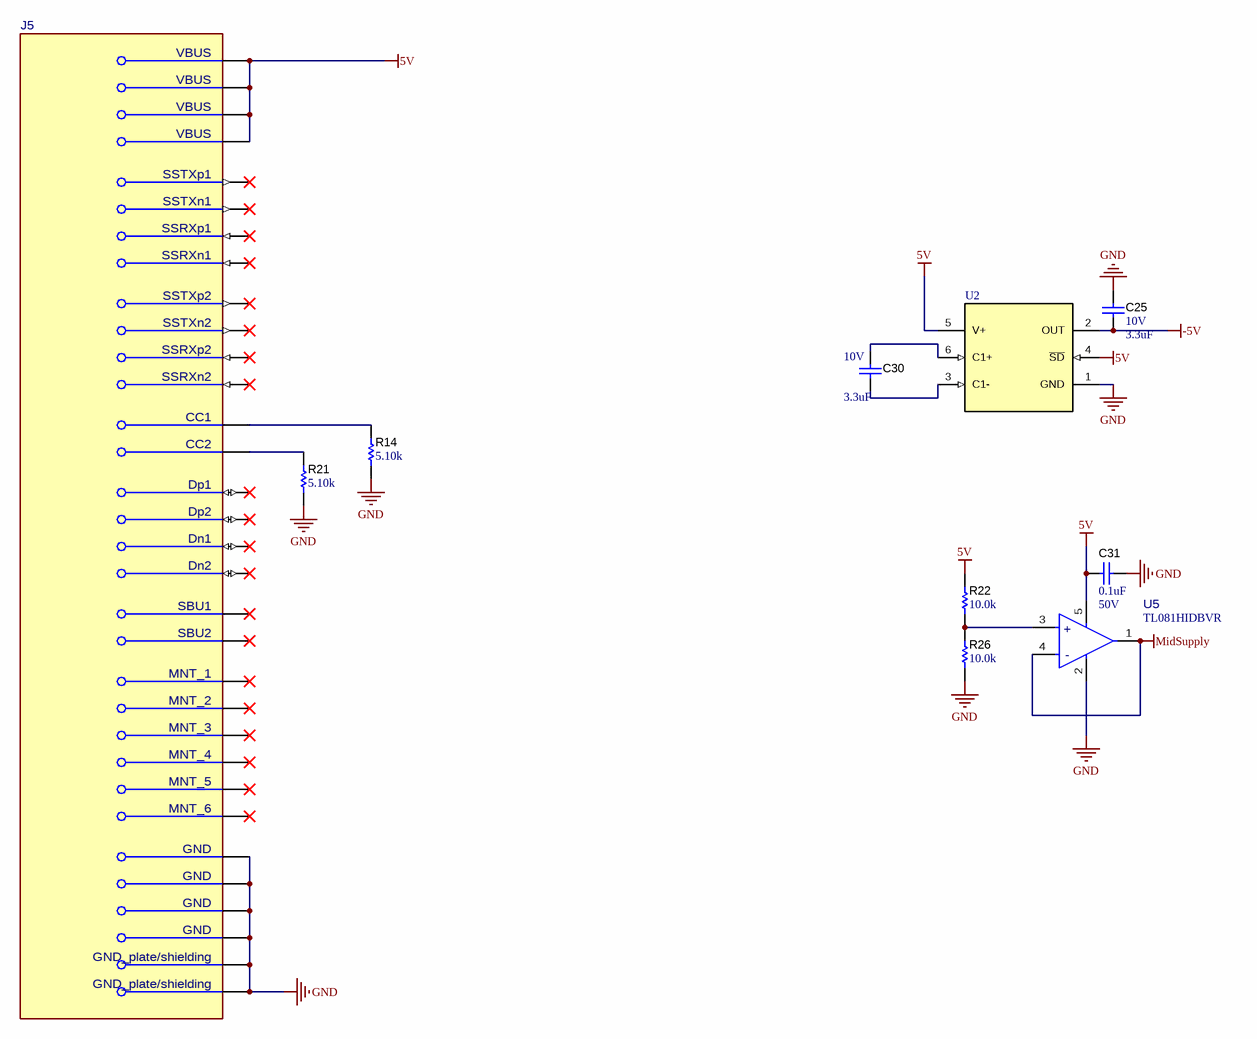
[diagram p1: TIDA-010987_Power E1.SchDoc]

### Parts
C25  VDC_V: 10V  ValueDisplayed: 3.3uF  [0603]  (hidden comment: C1608X7S1A335K080AC)
C30  VDC_V: 10V  ValueDisplayed: 3.3uF  [0603]  (hidden comment: C1608X7S1A335K080AC)
C31  value 0.1uF  VDC_V: 50V  [0603]  (hidden comment: 06035C104JAT2A)
J5  632723300011  [FP-632723300011_CONN_USB_8MM74_11MM20-MFG]  (value not drawn)
R14  ValueDisplayed: 5.10k  [0603]  (hidden comment: RG1608P-512-B-T5)
R21  ValueDisplayed: 5.10k  [0603]  (hidden comment: RG1608P-512-B-T5)
R22  ValueDisplayed: 10.0k  [0603]  (hidden comment: M55342K12B10E0T)
R26  ValueDisplayed: 10.0k  [0603]  (hidden comment: M55342K12B10E0T)
U2  LM2664M6/NOPB  [DBV0006A_N]  (value not drawn)
U5  TL081HIDBVR  [DBV0005A-MFG]

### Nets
5V: C31.1 J5.A4(VBUS) J5.A9(VBUS) J5.B4(VBUS) J5.B9(VBUS) R22.2 U2.4(~{SD}) U2.5(V+) U5.5(V+)
-5V: C25.2 U2.2(OUT)
GND: C25.1 C31.2 J5.1(GND_plate/shielding) J5.2(GND_plate/shielding) J5.A1(GND) J5.A12(GND) J5.B1(GND) J5.B12(GND) R14.2 R21.2 R26.1 U2.1(GND) U5.2(V-)
MidSupply: U5.1(OUT) U5.4(IN-)
NetC30_1: C30.1 U2.3(C1-)
NetC30_2: C30.2 U2.6(C1+)
NetJ5_A5: J5.A5(CC1) R14.1
NetJ5_B5: J5.B5(CC2) R21.1
NetR22_1: R22.1 R26.2 U5.3(IN+)

Not connected (* = marked no-connect by the designer): J5 3(MNT_1)* 4(MNT_2)* 5(MNT_3)* 6(MNT_4)* 7(MNT_5)* 8(MNT_6)* A2(SSTXp1)* A3(SSTXn1)* A6(Dp1)* A7(Dn1)* A8(SBU1)* A10(SSRXn2)* A11(SSRXp2)* B2(SSTXp2)* B3(SSTXn2)* B6(Dp2)* B7(Dn2)* B8(SBU2)* B10(SSRXn1)* B11(SSRXp1)*

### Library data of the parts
C25 C30 = CMP-0007057-4: CAP, CERM, 3.3 uF, 10 V, +/- 10%, X7S, 0603; Manufacturer: TDK; TaMin_C: -55°C; ESR_ohm: 4.796m; Polarized: N; SizeAreaWB_mm2: 4.68; Value1: 0.004796 ohm; U/M: EA; Value: 3.3uF; TaMax_C: 125°C; SizeZ_mm: 1; SizeX_mm: 1.6; SizeY_mm: 0.8; SizeArea_mm2: 1.28; Cap_F: 3.3µF; IRMS_A: 2.3752A; AEC Category: Q200
C31 = CMP-0083854-1: as C7 on sheet TIDA-010987_AFE E1
J5 = CMP-0091586-1: USB-C (USB TYPE-C) USB 3.2 Gen 2 (USB 3.1 Gen 2, Superspeed + (USB 3.1)) Receptacle Connector 24 Position Surface Mount, Right Angle; Through Hole; Manufacturer: Wurth; AEC Qualified: No; Shrouded: true; SizeZ_mm: 3.41mm; Is Female: yes; Usb Standard: USB 3.1; Voltage_V: 20V; ContactFinish: Gold,Nickel; Conn Orientation: Horizontal; Standoff Height: 0.1mm; Current_A: 5A
R14 R21 = CMP-0023568-3: RES, 5.10 k, 0.1%, 0.1 W, 0603; Manufacturer: Susumu Co Ltd; Power_W: 100mW; TempCo: 25 ppm/C; Value_Code: 5k10; Value: 5.10k; Res_ohm: 5.1k; SizeX_mm: 1.6; SizeY_mm: 0.8; SizeZ_mm: 1; Value2: 0.1W; SizeArea_mm2: 1.28; VDC_V: 75V; AEC Category: Q200; U/M: EA
R22 R26 = CMP-0080488-1: RES, 10.0 k, 1%, 0.1 W, 0603; Manufacturer: TT Electronics/IRC; Power_W: 100mW; TempCo: 100 ppm/C; SizeAreaWB_mm2: 4.68; Value_Code: 10k0; Value: 10.0k; EIA_Code: E96; Res_ohm: 10k; SizeX_mm: 1.6; SizeY_mm: 0.8; SizeZ_mm: 1; Value2: 0.1W; SizeArea_mm2: 1.28; AEC Qualified: N; AEC Category: Q200
U2 = CMP-0072145-1: Switched Capacitor Voltage Converter, 6-pin SOT-23, Pb-Free; Manufacturer: Texas Instruments; CompType: Switch Caps; PowerWise: N; PackageTopMarking: S03A*XTT
U5 = CMP-0123245-1: Single, 40-V, 5.25-MHz, 4-mV offset voltage, 20-V/µs, In to V+ op amp with -40°C to 125°C operation; Manufacturer: Texas Instruments; SizeZ_mm: 1.45mm; AEC Qualified: No; Gain Bandwidth: 5.25MHz; Input Bias Current: 1pA; Input Offset Voltage: 1mV; Max Supply Voltage: 40V; Min Supply Voltage: 4.5V; Nominal Supply Current: 960uA; Number Of Channels: 1; Output Current Per Channel: 26mA; Response Time: 0.91us; Standoff Height: 0mm; TaMax_C: +125°C; TJmax_C: +150°C; Voltage Gain: 125dB

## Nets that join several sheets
5V: TIDA-010987_AFE E1 (7 pins), TIDA-010987_Power E1 (9 pins)
-5V: TIDA-010987_AFE E1 (6 pins), TIDA-010987_Power E1 (C25.2 U2.2)
GND: TIDA-010987_AFE E1 (28 pins), TIDA-010987_Power E1 (13 pins)
MidSupply: TIDA-010987_AFE E1 (5 pins), TIDA-010987_Power E1 (U5.1 U5.4)

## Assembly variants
001: all parts fitted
